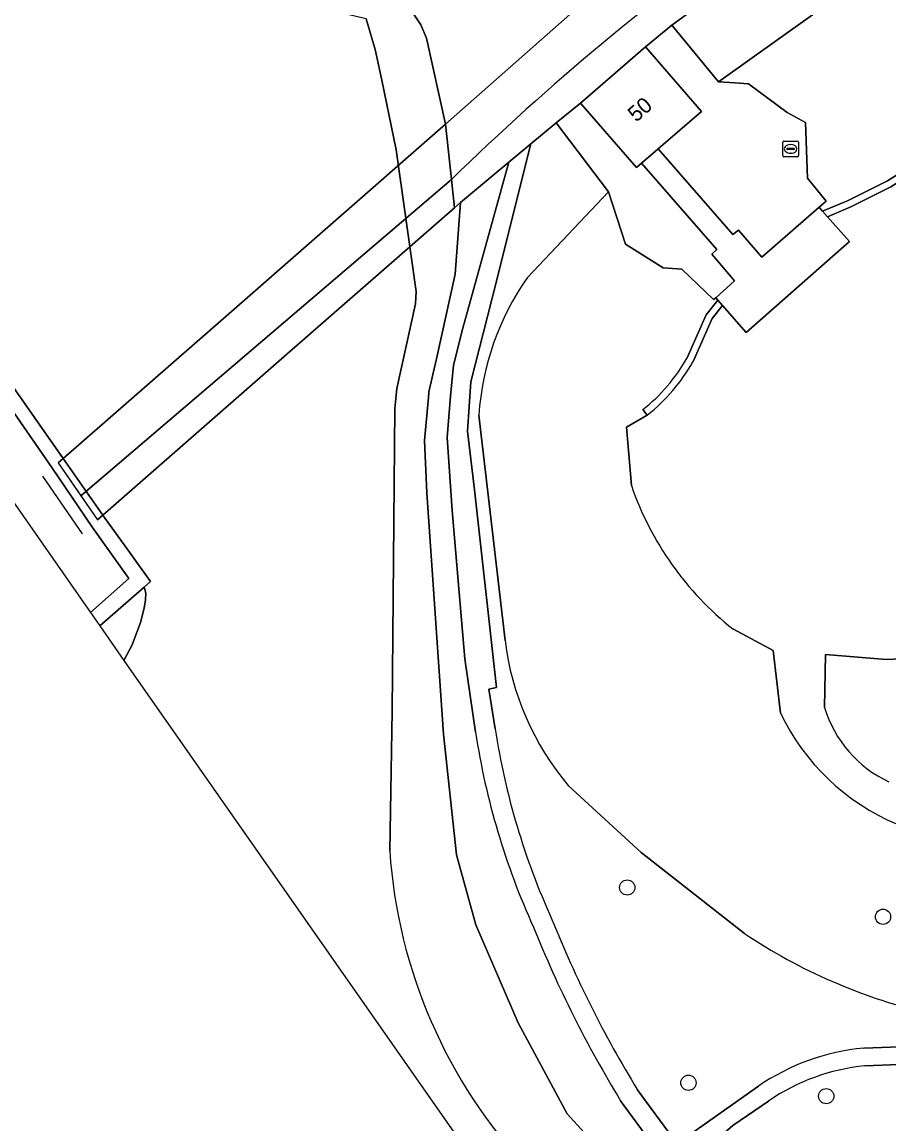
# Model space of a CAD drawing. Extents: x 155640 to 156811, y 382821 to 384049.
# Drawn here: x 156106.4 to 156162, y 383326 to 383396.7 of the extents above; entities that cross this region are included whole.
import ezdxf

# ---------------------------------------------------------------- set-up
doc = ezdxf.new("R2010")
doc.units = 0
for name, color, linetype in [('IMGEO_Boom', 7, 'Continuous'), ('IMGEO_Dek', 7, 'Continuous'), ('IMGEO_Fietspad_gesloten', 7, 'Continuous'), ('IMGEO_Gemaal', 7, 'Continuous'), ('IMGEO_Groenvoorziening', 7, 'Continuous'), ('IMGEO_Hek', 7, 'Continuous'), ('IMGEO_Lijnafwatering', 7, 'Continuous'), ('IMGEO_Meer_plas_ven_vijver', 7, 'Continuous'), ('IMGEO_Muur', 7, 'Continuous'), ('IMGEO_Oever', 7, 'Continuous'), ('IMGEO_Pand', 7, 'Continuous'), ('IMGEO_Pand_nummerreeks', 7, 'Continuous'), ('IMGEO_Rijbaan_lokaal_gesloten', 7, 'Continuous'), ('IMGEO_Rioolput', 7, 'Continuous'), ('IMGEO_Terreindeel_halfverhard', 7, 'Continuous'), ('IMGEO_Voetpad_gesloten', 7, 'Continuous'), ('IMGEO_Voetpad_halfverhard', 7, 'Continuous'), ('IMGEO_Waterloop', 7, 'Continuous')]:
    doc.layers.add(name, color=color, linetype=linetype)

msp = doc.modelspace()

# ---------------------------------------------------------------- linework, layer by layer
at = {"layer": 'IMGEO_Boom'}
for centre in [(156145.251, 383341.154), (156161.668, 383339.278), (156149.18, 383328.631), (156158.021, 383327.77)]:
    msp.add_circle(centre, 0.489, dxfattribs=at)
at = {"layer": 'IMGEO_Dek'}
msp.add_lwpolyline([(156134.157, 383384.762), (156133.968, 383386.568), (156133.596, 383390.126), (156118.821, 383377.212), (156109.06, 383368.68), (156108.724, 383368.387), (156111.249, 383364.738), (156123.585, 383375.521)], close=True, dxfattribs=at)
at = {"layer": 'IMGEO_Fietspad_gesloten'}
msp.add_lwpolyline([(156155.165, 383407.873), (156152.157, 383405.752), (156151.469, 383405.227), (156150.234, 383404.285), (156149.197, 383403.522), (156147.705, 383402.278), (156141.94, 383397.47), (156133.596, 383390.126), (156133.968, 383386.568)], dxfattribs=at)
msp.add_lwpolyline([(156133.968, 383386.568), (156133.596, 383390.126), (156118.821, 383377.212), (156109.06, 383368.68), (156108.724, 383368.387), (156110.178, 383366.285)], close=True, dxfattribs=at)
msp.add_arc((156250.069, 383267.463), 166.329, 125.23475, 134.2683, dxfattribs=at)
at = {"layer": 'IMGEO_Gemaal'}
msp.add_lwpolyline([(156159.514, 383382.592), (156158.104, 383384.186), (156157.789, 383384.541), (156157.565, 383384.795), (156153.893, 383381.595), (156152.395, 383383.33), (156152.034, 383383.035), (156147.236, 383388.53), (156146.171, 383387.612), (156151.003, 383382.09), (156150.679, 383381.786), (156152.136, 383380.074), (156150.929, 383378.989), (156151.067, 383378.831), (156151.368, 383378.487), (156152.887, 383376.748)], close=True, dxfattribs=at)
at = {"layer": 'IMGEO_Groenvoorziening'}
for points in [[(156151.87, 383399.225), (156148.104, 383396.467), (156151.107, 383392.841), (156161.309, 383400.137), (156169.113, 383405.2), (156185.085, 383411.881), (156193.51, 383414.012), (156208.371, 383415.127), (156220.213, 383413.56), (156218.012, 383419.252), (156217.917, 383428.03), (156219.181, 383438.039)], [(156138.846, 383380.287), (156144.04, 383385.778), (156140.702, 383390.214), (156139.066, 383388.852), (156136.578, 383378.952), (156135.223, 383373.592), (156134.997, 383370.43), (156135.448, 383366.666), (156136.859, 383353.981), (156136.366, 383353.868), (156136.783, 383351.339)], [(156135.516, 383351.12), (156134.832, 383355.829), (156134.009, 383365.345), (156133.703, 383370.02), (156133.909, 383372.668), (156134.114, 383374.66), (156134.709, 383377.042), (156137.653, 383387.676), (156134.561, 383385.102), (156134.214, 383380.489), (156133.002, 383375.06), (156132.529, 383372.943), (156132.497, 383372.59), (156132.246, 383369.832), (156132.396, 383366.467), (156133.47, 383350.981), (156134.287, 383343.243), (156135.541, 383338.758), (156138.246, 383332.465), (156141.401, 383326.636), (156145.769, 383321.853), (156154.762, 383312.004), (156158.12, 383305.723), (156158.972, 383299.529)], [(156137.412, 383357.005), (156135.73, 383371.449)], [(156152.775, 383338.211), (156146.139, 383343.41), (156141.461, 383347.699)], [(156160.427, 383330.857), (156162.718, 383330.942), (156179.341, 383330.163), (156183.511, 383330.317), (156192.994, 383331.249)], [(156193.128, 383330.109), (156183.586, 383329.172), (156179.339, 383329.015), (156168.196, 383329.536), (156162.71, 383329.793), (156160.503, 383329.712)], [(156145.893, 383328.197), (156147.915, 383325.436), (156149.181, 383325.447), (156149.472, 383325.45), (156153.666, 383328.407)], [(156146.894, 383324.657), (156144.825, 383327.482)], [(156154.314, 383327.46), (156152.02, 383325.893), (156150.365, 383324.438), (156150.109, 383322.933), (156151.778, 383321.422), (156155.12, 383318.463)]]:
    msp.add_lwpolyline(points, dxfattribs=at)
msp.add_lwpolyline([(156136.516, 383401.856), (156134.46, 383400.218), (156133.381, 383399.814), (156131.77, 383399.125), (156130.884, 383398.596), (156130.721, 383398.487), (156130.781, 383398.32), (156132.003, 383396.492), (156132.363, 383395.636), (156133.596, 383390.126), (156141.94, 383397.47), (156147.705, 383402.278), (156147.798, 383405.436), (156146.238, 383407.622), (156145.365, 383407.332), (156141.269, 383405.97), (156134.048, 383406.056), (156134.743, 383405.312), (156135.412, 383404.532), (156136.234, 383403.172), (156136.554, 383402.297)], close=True, dxfattribs=at)
for centre, radius, start, end in [((156153.039, 383370.315), 17.346, 144.9075, 176.25042), ((156155.074, 383359.156), 17.792, 186.94302, 220.08428), ((156182.75, 383358.365), 47.786, 188.7208, 204.42722), ((156182.635, 383358.326), 46.382, 188.66391, 204.47652), ((156208.706, 383366.517), 73.579, 201.86992, 211.38613), ((156208.621, 383366.474), 74.768, 201.88583, 211.43369), ((156172.463, 383367.491), 35.283, 236.08303, 246.48299), ((156172.487, 383367.557), 35.353, 246.49009, 256.39057), ((156161.771, 383316.593), 14.327, 95.38417, 124.45407), ((156161.772, 383316.594), 13.179, 95.52529, 124.46471)]:
    msp.add_arc(centre, radius, start, end, dxfattribs=at)
at = {"layer": 'IMGEO_Hek'}
for points in [[(156118.821, 383377.212), (156133.596, 383390.126)], [(156134.157, 383384.762), (156123.585, 383375.521)], [(156109.06, 383368.68), (156118.821, 383377.212)], [(156123.585, 383375.521), (156111.249, 383364.738)], [(156108.724, 383368.387), (156109.06, 383368.68)]]:
    msp.add_lwpolyline(points, dxfattribs=at)
at = {"layer": 'IMGEO_Lijnafwatering'}
msp.add_lwpolyline([(156107.726, 383367.537), (156110.273, 383363.837)], dxfattribs=at)
at = {"layer": 'IMGEO_Meer_plas_ven_vijver'}
for points in [[(156130.013, 383343.499), (156130.177, 383352.47), (156130.34, 383371.887), (156130.463, 383373.157), (156131.672, 383378.605), (156131.713, 383379.383), (156130.422, 383388.477), (156129.501, 383392.942), (156129.07, 383394.909), (156128.497, 383396.875), (156106.721, 383402.018), (156096.954, 383385.924)], [(156097.843, 383384.658), (156109.06, 383368.68), (156111.754, 383364.818), (156113.301, 383362.676), (156114.667, 383360.783), (156114.259, 383360.426), (156114.354, 383360.038), (156114.344, 383359.598), (156114.262, 383359.066), (156114.016, 383358.144), (156113.484, 383356.731), (156112.955, 383355.726), (156143.645, 383311.87)]]:
    msp.add_lwpolyline(points, dxfattribs=at)
msp.add_arc((156162.903, 383345.692), 32.963, 183.81443, 223.16706, dxfattribs=at)
at = {"layer": 'IMGEO_Muur'}
for points in [[(156158.104, 383384.186), (156159.609, 383384.822), (156162.165, 383386.097), (156162.862, 383386.534), (156164.566, 383388.076), (156164.264, 383388.41), (156162.589, 383386.894), (156161.945, 383386.49), (156159.421, 383385.231), (156157.789, 383384.541)], [(156093.734, 383383.193), (156094.245, 383382.462), (156096.82, 383384.7), (156108.334, 383368.095), (156110.934, 383364.252), (156113.278, 383360.976), (156110.811, 383358.79), (156111.412, 383357.931), (156114.259, 383360.426), (156114.667, 383360.783), (156113.301, 383362.676), (156111.754, 383364.818), (156109.06, 383368.68), (156097.843, 383384.658), (156096.954, 383385.924), (156096.164, 383385.254), (156094.011, 383383.428)]]:
    msp.add_lwpolyline(points, close=True, dxfattribs=at)
for points in [[(156149.475, 383374.896), (156150.699, 383377.646), (156151.368, 383378.487), (156151.067, 383378.831), (156150.311, 383377.881), (156149.073, 383375.099)], [(156146.259, 383371.81), (156146.539, 383371.458)]]:
    msp.add_lwpolyline(points, dxfattribs=at)
for centre, radius, start, end in [((156139.195, 383380.702), 11.356, 308.46351, 330.43727), ((156139.227, 383380.675), 11.765, 308.42556, 330.58079)]:
    msp.add_arc(centre, radius, start, end, dxfattribs=at)
at = {"layer": 'IMGEO_Oever'}
for points in [[(156225.419, 383412.87), (156225.396, 383412.874), (156220.213, 383413.56), (156208.371, 383415.127), (156193.51, 383414.012), (156185.085, 383411.881), (156169.113, 383405.2), (156161.309, 383400.137), (156151.107, 383392.841), (156152.155, 383392.772), (156153.041, 383392.714), (156155.519, 383390.868), (156156.694, 383390.224), (156156.829, 383386.666), (156158.018, 383385.171), (156157.565, 383384.795), (156157.789, 383384.541), (156159.421, 383385.231), (156161.945, 383386.49), (156162.589, 383386.894), (156164.264, 383388.41), (156164.566, 383388.076), (156165.611, 383389.014), (156167.471, 383389.93)], [(156145.769, 383321.853), (156141.401, 383326.636), (156138.246, 383332.465), (156135.541, 383338.758), (156134.287, 383343.243), (156133.47, 383350.981), (156132.396, 383366.467), (156132.246, 383369.832), (156132.497, 383372.59), (156132.529, 383372.943), (156133.002, 383375.06), (156134.214, 383380.489), (156134.561, 383385.102), (156134.157, 383384.762), (156133.968, 383386.568), (156133.596, 383390.126), (156132.363, 383395.636), (156132.003, 383396.492), (156130.781, 383398.32)], [(156128.497, 383396.875), (156129.07, 383394.909), (156129.501, 383392.942), (156130.422, 383388.477), (156131.713, 383379.383), (156131.672, 383378.605), (156130.463, 383373.157), (156130.34, 383371.887), (156130.177, 383352.47), (156130.013, 383343.499)], [(156149.073, 383375.099), (156150.311, 383377.881), (156151.067, 383378.831), (156150.929, 383378.989), (156150.793, 383378.875), (156148.76, 383380.822), (156147.569, 383380.895), (156145.136, 383382.425), (156144.04, 383385.778), (156138.846, 383380.287)], [(156135.73, 383371.449), (156137.412, 383357.005)], [(156145.517, 383366.943), (156145.211, 383370.68), (156146.539, 383371.458), (156146.259, 383371.81)], [(156111.412, 383357.931), (156112.955, 383355.726), (156113.484, 383356.731), (156114.016, 383358.144), (156114.262, 383359.066), (156114.344, 383359.598), (156114.354, 383360.038), (156114.259, 383360.426), (156111.412, 383357.931)], [(156155.08, 383352.348), (156154.627, 383356.362), (156152.033, 383357.744)], [(156174.896, 383355.435), (156171.304, 383357.299), (156168.46, 383358.1), (156165.093, 383355.939), (156161.867, 383355.783), (156157.986, 383356.104), (156157.915, 383352.703)], [(156141.461, 383347.699), (156146.139, 383343.41), (156152.775, 383338.211)]]:
    msp.add_lwpolyline(points, dxfattribs=at)
for centre, radius, start, end in [((156153.039, 383370.315), 17.346, 144.9075, 176.25042), ((156139.195, 383380.702), 11.356, 308.46351, 330.43727), ((156164.574, 383373.534), 20.164, 199.0793, 231.54348), ((156155.074, 383359.156), 17.792, 186.94302, 220.08428), ((156168.197, 383358.63), 14.543, 205.59174, 247.11947), ((156165.272, 383354.909), 7.681, 196.68868, 245.18767), ((156162.903, 383345.692), 32.963, 183.81443, 223.16706), ((156172.463, 383367.491), 35.283, 236.08303, 246.48299), ((156172.487, 383367.557), 35.353, 246.49009, 256.39057)]:
    msp.add_arc(centre, radius, start, end, dxfattribs=at)
at = {"layer": 'IMGEO_Pand'}
msp.add_lwpolyline([(156150.02, 383390.931), (156146.424, 383395.084), (156142.254, 383391.471), (156145.846, 383387.332), (156146.171, 383387.612), (156147.236, 383388.53)], close=True, dxfattribs=at)
at = {"layer": 'IMGEO_Rijbaan_lokaal_gesloten'}
msp.add_lwpolyline([(156098.433, 383376.478), (156098.665, 383376.671), (156099.983, 383375.084), (156099.619, 383374.782), (156102.884, 383370.117), (156103.053, 383370.264), (156104.35, 383368.772), (156104.024, 383368.488), (156110.811, 383358.79), (156113.278, 383360.976), (156110.934, 383364.252), (156108.334, 383368.095), (156096.82, 383384.7), (156094.245, 383382.462), (156098.433, 383376.478)], dxfattribs=at)
at = {"layer": 'IMGEO_Rioolput'}
for p, q in [((156155.234, 383388.108), (156155.234, 383388.96)), ((156155.309, 383389.034), (156156.161, 383389.034)), ((156156.235, 383388.96), (156156.235, 383388.108)), ((156155.493, 383388.528), (156155.493, 383388.54)), ((156155.931, 383388.491), (156155.533, 383388.491)), ((156155.536, 383388.577), (156155.934, 383388.577)), ((156155.745, 383388.254), (156155.72, 383388.254)), ((156155.722, 383388.814), (156155.747, 383388.814)), ((156155.977, 383388.54), (156155.977, 383388.528)), ((156156.161, 383388.034), (156155.309, 383388.034))]:
    msp.add_line(p, q, dxfattribs=at)
for points in [[(156155.234, 383388.108), (156155.234, 383388.96)], [(156155.309, 383389.034), (156156.161, 383389.034)], [(156156.235, 383388.96), (156156.235, 383388.108)], [(156156.161, 383388.034), (156155.309, 383388.034)]]:
    msp.add_lwpolyline(points, dxfattribs=at)
for centre, radius, start, end in [((156155.311, 383388.958), 0.0765, 91.55205, 178.44795), ((156155.311, 383388.958), 0.0765, 91.55205, 178.44795), ((156156.159, 383388.958), 0.0765, 1.55205, 88.44795), ((156156.159, 383388.958), 0.0765, 1.55205, 88.44795), ((156155.533, 383388.537), 0.0403, 85.87752, 175.75265), ((156155.53, 383388.527), 0.0366, 178.93798, 274.71019), ((156155.934, 383388.534), 0.043, 264.86636, 352.45326), ((156155.938, 383388.539), 0.0386, 1.73085, 96.63898), ((156155.311, 383388.11), 0.0765, 181.55205, 268.44795), ((156155.311, 383388.11), 0.0765, 181.55205, 268.44795), ((156156.159, 383388.11), 0.0765, 271.55205, 358.44795), ((156156.159, 383388.11), 0.0765, 271.55205, 358.44795)]:
    msp.add_arc(centre, radius, start, end, dxfattribs=at)
for centre, major_axis, ratio, start_param, end_param in [((156155.721, 383388.534), (-0.387, 0.002), 0.722429, 4.712389, 7.853982), ((156155.746, 383388.534), (-0.39, 0.002), 0.717154, 1.570796, 4.712389)]:
    msp.add_ellipse(centre, major_axis=major_axis, ratio=ratio, start_param=start_param, end_param=end_param, dxfattribs=at)
at = {"layer": 'IMGEO_Terreindeel_halfverhard'}
for points in [[(156151.107, 383392.841), (156148.104, 383396.467), (156146.424, 383395.084), (156150.02, 383390.931), (156147.236, 383388.53), (156152.034, 383383.035), (156152.395, 383383.33), (156153.893, 383381.595), (156157.565, 383384.795), (156158.018, 383385.171), (156156.829, 383386.666), (156156.694, 383390.224), (156155.519, 383390.868), (156153.041, 383392.714), (156152.155, 383392.772)], [(156145.846, 383387.332), (156142.254, 383391.471), (156140.702, 383390.214), (156144.04, 383385.778), (156145.136, 383382.425), (156147.569, 383380.895), (156148.76, 383380.822), (156150.793, 383378.875), (156150.929, 383378.989), (156152.136, 383380.074), (156150.679, 383381.786), (156151.003, 383382.09), (156146.171, 383387.612)]]:
    msp.add_lwpolyline(points, close=True, dxfattribs=at)
at = {"layer": 'IMGEO_Voetpad_gesloten'}
msp.add_lwpolyline([(156133.968, 383386.568), (156134.157, 383384.762), (156134.561, 383385.102), (156137.653, 383387.676), (156139.066, 383388.852), (156140.702, 383390.214), (156142.254, 383391.471), (156146.424, 383395.084), (156148.104, 383396.467), (156151.87, 383399.225)], dxfattribs=at)
msp.add_lwpolyline([(156134.157, 383384.762), (156133.968, 383386.568), (156110.178, 383366.285), (156111.249, 383364.738), (156123.585, 383375.521)], close=True, dxfattribs=at)
msp.add_arc((156250.069, 383267.463), 166.329, 125.23475, 134.2683, dxfattribs=at)
at = {"layer": 'IMGEO_Voetpad_halfverhard'}
for points in [[(156136.783, 383351.339), (156136.366, 383353.868), (156136.859, 383353.981), (156135.448, 383366.666), (156134.997, 383370.43), (156135.223, 383373.592), (156136.578, 383378.952), (156139.066, 383388.852), (156137.653, 383387.676), (156134.709, 383377.042), (156134.114, 383374.66), (156133.909, 383372.668), (156133.703, 383370.02), (156134.009, 383365.345), (156134.832, 383355.829), (156135.516, 383351.12)], [(156192.994, 383331.249), (156183.511, 383330.317), (156179.341, 383330.163), (156162.718, 383330.942), (156160.427, 383330.857)], [(156160.503, 383329.712), (156162.71, 383329.793), (156168.196, 383329.536), (156179.339, 383329.015), (156183.586, 383329.172), (156193.128, 383330.109)], [(156155.12, 383318.463), (156151.778, 383321.422), (156150.109, 383322.933), (156147.915, 383325.436), (156145.893, 383328.197)], [(156153.666, 383328.407), (156149.472, 383325.45), (156149.181, 383325.447), (156147.915, 383325.436), (156150.109, 383322.933), (156150.365, 383324.438), (156152.02, 383325.893), (156154.314, 383327.46)], [(156144.825, 383327.482), (156146.894, 383324.657)]]:
    msp.add_lwpolyline(points, dxfattribs=at)
for centre, radius, start, end in [((156182.75, 383358.365), 47.786, 188.7208, 204.42722), ((156182.635, 383358.326), 46.382, 188.66391, 204.47652), ((156208.706, 383366.517), 73.579, 201.86992, 211.38613), ((156208.621, 383366.474), 74.768, 201.88583, 211.43369), ((156161.771, 383316.593), 14.327, 95.38417, 124.45407), ((156161.772, 383316.594), 13.179, 95.52529, 124.46471)]:
    msp.add_arc(centre, radius, start, end, dxfattribs=at)
at = {"layer": 'IMGEO_Waterloop'}
for points in [[(156167.471, 383389.93), (156165.611, 383389.014), (156164.566, 383388.076), (156162.862, 383386.534), (156162.165, 383386.097), (156159.609, 383384.822), (156158.104, 383384.186), (156159.514, 383382.592), (156152.887, 383376.748), (156151.368, 383378.487), (156150.699, 383377.646), (156149.475, 383374.896)], [(156146.539, 383371.458), (156145.211, 383370.68), (156145.517, 383366.943)], [(156152.033, 383357.744), (156154.627, 383356.362), (156155.08, 383352.348)], [(156157.915, 383352.703), (156157.986, 383356.104), (156161.867, 383355.783), (156165.093, 383355.939), (156168.46, 383358.1), (156171.304, 383357.299), (156174.896, 383355.435)]]:
    msp.add_lwpolyline(points, dxfattribs=at)
for centre, radius, start, end in [((156139.227, 383380.675), 11.765, 308.42556, 330.58079), ((156164.574, 383373.534), 20.164, 199.0793, 231.54348), ((156168.197, 383358.63), 14.543, 205.59174, 247.11947), ((156165.272, 383354.909), 7.681, 196.68868, 245.18767)]:
    msp.add_arc(centre, radius, start, end, dxfattribs=at)

# ---------------------------------------------------------------- texts
at = {"layer": 'IMGEO_Pand_nummerreeks'}
msp.add_text('50', height=1, rotation=41.06961, dxfattribs=at).set_placement((156145.828, 383390.209))

doc.saveas('drawing.dxf')
